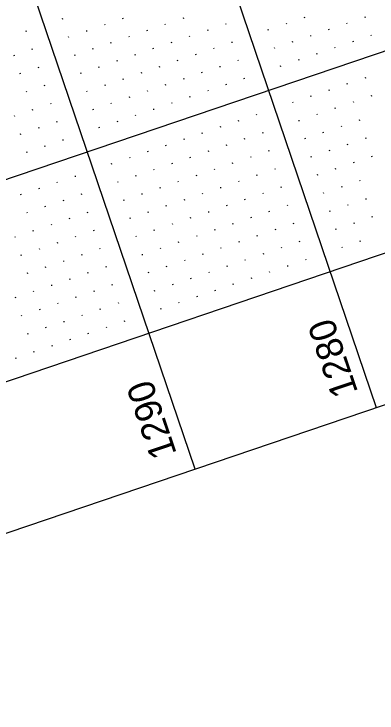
# Model space of a CAD drawing. Extents: x 2150318 to 2152065, y 143281 to 145371.
# Drawn here: x 2151642.9 to 2151737.7, y 143675.5 to 143858.1 of the extents above; entities that cross this region are included whole.
import ezdxf

# ---------------------------------------------------------------- set-up
doc = ezdxf.new("R2010")
doc.units = 0
for name, color, linetype in [('SHT_Plan_Profile_Sheet_Elev_Txt', 7, 'Continuous'), ('SHT_Profile_Grid_Major', 7, 'Continuous'), ('SHT_Profile_Grid_Minor', 7, 'Continuous'), ('SHT_Sheet_Border', 7, 'Continuous')]:
    doc.layers.add(name, color=color, linetype=linetype)

msp = doc.modelspace()

# ---------------------------------------------------------------- linework, layer by layer
at = {"layer": 'SHT_Profile_Grid_Major'}
for p, q in [((2151737.57, 143755.28), (2151231.58, 145246.79)), ((2151690.22, 143739.22), (2151184.23, 145230.73)), ((2151851.5, 143886.33), (2151378.01, 143725.7))]:
    msp.add_line(p, q, dxfattribs=at)
at = {"layer": 'SHT_Profile_Grid_Minor'}
for p, q in [((2151655.64, 143856.71), (2151655.56, 143856.95)), ((2151671.45, 143856.8), (2151671.37, 143857.03)), ((2151687.26, 143856.88), (2151687.18, 143857.12)), ((2151718.88, 143857.05), (2151718.8, 143857.28)), ((2151734.69, 143857.13), (2151734.61, 143857.37)), ((2151666.71, 143855.19), (2151666.63, 143855.43)), ((2151682.52, 143855.27), (2151682.44, 143855.51)), ((2151698.33, 143855.36), (2151698.25, 143855.59)), ((2151714.15, 143855.44), (2151714.07, 143855.68)), ((2151729.96, 143855.53), (2151729.88, 143855.76)), ((2151646.17, 143853.5), (2151646.09, 143853.74)), ((2151661.98, 143853.58), (2151661.9, 143853.82)), ((2151677.79, 143853.67), (2151677.71, 143853.9)), ((2151693.6, 143853.75), (2151693.52, 143853.99)), ((2151709.41, 143853.84), (2151709.33, 143854.07)), ((2151725.22, 143853.92), (2151725.14, 143854.16)), ((2151657.24, 143851.98), (2151657.16, 143852.21)), ((2151673.05, 143852.06), (2151672.97, 143852.3)), ((2151688.86, 143852.14), (2151688.78, 143852.38)), ((2151720.49, 143852.31), (2151720.41, 143852.55)), ((2151736.3, 143852.4), (2151736.22, 143852.63)), ((2151668.32, 143850.45), (2151668.24, 143850.69)), ((2151684.13, 143850.54), (2151684.05, 143850.78)), ((2151699.94, 143850.62), (2151699.86, 143850.86)), ((2151715.75, 143850.71), (2151715.67, 143850.94)), ((2151731.56, 143850.79), (2151731.48, 143851.03)), ((2151647.77, 143848.76), (2151647.69, 143849)), ((2151663.58, 143848.85), (2151663.5, 143849.09)), ((2151679.39, 143848.93), (2151679.31, 143849.17)), ((2151695.21, 143849.02), (2151695.13, 143849.25)), ((2151711.02, 143849.1), (2151710.94, 143849.34)), ((2151722.09, 143847.58), (2151722.01, 143847.81)), ((2151726.83, 143849.18), (2151726.75, 143849.42)), ((2151643.04, 143847.16), (2151642.96, 143847.39)), ((2151658.85, 143847.24), (2151658.77, 143847.48)), ((2151669.92, 143845.72), (2151669.84, 143845.96)), ((2151674.66, 143847.33), (2151674.58, 143847.56)), ((2151685.74, 143845.8), (2151685.66, 143846.04)), ((2151690.47, 143847.41), (2151690.39, 143847.65)), ((2151701.55, 143845.89), (2151701.47, 143846.12)), ((2151717.36, 143845.97), (2151717.28, 143846.21)), ((2151649.38, 143844.03), (2151649.3, 143844.27)), ((2151665.19, 143844.11), (2151665.11, 143844.35)), ((2151681, 143844.2), (2151680.92, 143844.43)), ((2151696.81, 143844.28), (2151696.73, 143844.52)), ((2151712.62, 143844.37), (2151712.54, 143844.6)), ((2151644.64, 143842.42), (2151644.56, 143842.66)), ((2151660.46, 143842.51), (2151660.37, 143842.74)), ((2151676.27, 143842.59), (2151676.19, 143842.83)), ((2151692.08, 143842.68), (2151692, 143842.91)), ((2151671.53, 143840.98), (2151671.45, 143841.22)), ((2151687.34, 143841.07), (2151687.26, 143841.31)), ((2151703.15, 143841.15), (2151703.07, 143841.39)), ((2151734.78, 143841.32), (2151734.7, 143841.56)), ((2151650.99, 143839.29), (2151650.9, 143839.53)), ((2151666.8, 143839.38), (2151666.72, 143839.62)), ((2151682.61, 143839.46), (2151682.53, 143839.7)), ((2151698.42, 143839.55), (2151698.34, 143839.78)), ((2151730.04, 143839.71), (2151729.96, 143839.95)), ((2151646.25, 143837.69), (2151646.17, 143837.92)), ((2151662.06, 143837.77), (2151661.98, 143838.01)), ((2151677.87, 143837.86), (2151677.79, 143838.09)), ((2151693.68, 143837.94), (2151693.6, 143838.18)), ((2151725.31, 143838.11), (2151725.23, 143838.34)), ((2151736.38, 143836.59), (2151736.3, 143836.82)), ((2151673.14, 143836.25), (2151673.06, 143836.49)), ((2151684.21, 143834.73), (2151684.13, 143834.96)), ((2151688.95, 143836.33), (2151688.87, 143836.57)), ((2151715.84, 143834.9), (2151715.76, 143835.13)), ((2151720.57, 143836.5), (2151720.49, 143836.74)), ((2151731.65, 143834.98), (2151731.57, 143835.22)), ((2151647.86, 143832.95), (2151647.78, 143833.19)), ((2151652.59, 143834.56), (2151652.51, 143834.8)), ((2151663.67, 143833.04), (2151663.59, 143833.27)), ((2151668.4, 143834.64), (2151668.32, 143834.88)), ((2151679.48, 143833.12), (2151679.4, 143833.36)), ((2151726.91, 143833.37), (2151726.83, 143833.61)), ((2151643.12, 143831.35), (2151643.04, 143831.58)), ((2151674.74, 143831.51), (2151674.66, 143831.75)), ((2151706.37, 143831.68), (2151706.29, 143831.92)), ((2151722.18, 143831.77), (2151722.1, 143832)), ((2151654.2, 143829.82), (2151654.12, 143830.06)), ((2151670.01, 143829.91), (2151669.93, 143830.15)), ((2151701.63, 143830.08), (2151701.55, 143830.31)), ((2151717.44, 143830.16), (2151717.36, 143830.4)), ((2151733.25, 143830.24), (2151733.17, 143830.48)), ((2151649.46, 143828.22), (2151649.38, 143828.46)), ((2151665.27, 143828.3), (2151665.19, 143828.54)), ((2151696.9, 143828.47), (2151696.82, 143828.71)), ((2151728.52, 143828.64), (2151728.44, 143828.87)), ((2151644.73, 143826.61), (2151644.65, 143826.85)), ((2151692.16, 143826.86), (2151692.08, 143827.1)), ((2151707.97, 143826.95), (2151707.89, 143827.18)), ((2151723.78, 143827.03), (2151723.7, 143827.27)), ((2151655.8, 143825.09), (2151655.72, 143825.33)), ((2151687.43, 143825.26), (2151687.35, 143825.49)), ((2151698.5, 143823.74), (2151698.42, 143823.97)), ((2151703.24, 143825.34), (2151703.16, 143825.58)), ((2151719.05, 143825.43), (2151718.97, 143825.66)), ((2151730.12, 143823.9), (2151730.04, 143824.14)), ((2151734.86, 143825.51), (2151734.78, 143825.75)), ((2151651.07, 143823.48), (2151650.99, 143823.72)), ((2151677.96, 143822.04), (2151677.88, 143822.28)), ((2151682.69, 143823.65), (2151682.61, 143823.89)), ((2151693.77, 143822.13), (2151693.69, 143822.37)), ((2151709.58, 143822.21), (2151709.5, 143822.45)), ((2151725.39, 143822.3), (2151725.31, 143822.53)), ((2151646.33, 143821.88), (2151646.25, 143822.11)), ((2151673.22, 143820.44), (2151673.14, 143820.68)), ((2151689.03, 143820.52), (2151688.95, 143820.76)), ((2151704.84, 143820.61), (2151704.76, 143820.84)), ((2151720.66, 143820.69), (2151720.57, 143820.93)), ((2151736.47, 143820.77), (2151736.39, 143821.01)), ((2151668.49, 143818.83), (2151668.41, 143819.07)), ((2151684.3, 143818.92), (2151684.22, 143819.15)), ((2151700.11, 143819), (2151700.03, 143819.24)), ((2151731.73, 143819.17), (2151731.65, 143819.41)), ((2151679.56, 143817.31), (2151679.48, 143817.55)), ((2151695.37, 143817.39), (2151695.29, 143817.63)), ((2151711.19, 143817.48), (2151711.1, 143817.71)), ((2151727, 143817.56), (2151726.92, 143817.8)), ((2151659.02, 143815.62), (2151658.94, 143815.86)), ((2151674.83, 143815.7), (2151674.75, 143815.94)), ((2151690.64, 143815.79), (2151690.56, 143816.02)), ((2151706.45, 143815.87), (2151706.37, 143816.11)), ((2151722.26, 143815.96), (2151722.18, 143816.19)), ((2151654.28, 143814.01), (2151654.2, 143814.25)), ((2151670.09, 143814.1), (2151670.01, 143814.33)), ((2151685.9, 143814.18), (2151685.82, 143814.42)), ((2151701.72, 143814.27), (2151701.63, 143814.5)), ((2151728.6, 143812.83), (2151728.52, 143813.06)), ((2151733.34, 143814.43), (2151733.26, 143814.67)), ((2151649.55, 143812.41), (2151649.47, 143812.64)), ((2151676.43, 143810.97), (2151676.35, 143811.21)), ((2151681.17, 143812.58), (2151681.09, 143812.81)), ((2151692.25, 143811.05), (2151692.16, 143811.29)), ((2151696.98, 143812.66), (2151696.9, 143812.9)), ((2151708.06, 143811.14), (2151707.98, 143811.37)), ((2151712.79, 143812.74), (2151712.71, 143812.98)), ((2151723.87, 143811.22), (2151723.79, 143811.46)), ((2151644.81, 143810.8), (2151644.73, 143811.04)), ((2151655.89, 143809.28), (2151655.81, 143809.52)), ((2151660.62, 143810.88), (2151660.54, 143811.12)), ((2151671.7, 143809.36), (2151671.62, 143809.6)), ((2151687.51, 143809.45), (2151687.43, 143809.68)), ((2151703.32, 143809.53), (2151703.24, 143809.77)), ((2151734.94, 143809.7), (2151734.86, 143809.94)), ((2151651.15, 143807.67), (2151651.07, 143807.91)), ((2151682.78, 143807.84), (2151682.7, 143808.08)), ((2151698.59, 143807.92), (2151698.51, 143808.16)), ((2151714.4, 143808.01), (2151714.32, 143808.24)), ((2151730.21, 143808.09), (2151730.13, 143808.33)), ((2151646.42, 143806.07), (2151646.34, 143806.3)), ((2151662.23, 143806.15), (2151662.15, 143806.39)), ((2151678.04, 143806.23), (2151677.96, 143806.47)), ((2151693.85, 143806.32), (2151693.77, 143806.55)), ((2151709.66, 143806.4), (2151709.58, 143806.64)), ((2151725.47, 143806.49), (2151725.39, 143806.72)), ((2151657.49, 143804.54), (2151657.41, 143804.78)), ((2151673.31, 143804.63), (2151673.23, 143804.86)), ((2151689.12, 143804.71), (2151689.04, 143804.95)), ((2151704.93, 143804.8), (2151704.85, 143805.03)), ((2151736.55, 143804.96), (2151736.47, 143805.2)), ((2151652.76, 143802.94), (2151652.68, 143803.17)), ((2151684.38, 143803.11), (2151684.3, 143803.34)), ((2151700.19, 143803.19), (2151700.11, 143803.43)), ((2151716, 143803.27), (2151715.92, 143803.51)), ((2151731.82, 143803.36), (2151731.73, 143803.59)), ((2151648.02, 143801.33), (2151647.94, 143801.57)), ((2151663.84, 143801.41), (2151663.76, 143801.65)), ((2151679.65, 143801.5), (2151679.57, 143801.74)), ((2151695.46, 143801.58), (2151695.38, 143801.82)), ((2151706.53, 143800.06), (2151706.45, 143800.3)), ((2151711.27, 143801.67), (2151711.19, 143801.9)), ((2151727.08, 143801.75), (2151727, 143801.99)), ((2151643.29, 143799.72), (2151643.21, 143799.96)), ((2151654.37, 143798.2), (2151654.29, 143798.44)), ((2151659.1, 143799.81), (2151659.02, 143800.05)), ((2151674.91, 143799.89), (2151674.83, 143800.13)), ((2151685.99, 143798.37), (2151685.91, 143798.61)), ((2151690.72, 143799.98), (2151690.64, 143800.21)), ((2151701.8, 143798.45), (2151701.72, 143798.69)), ((2151717.61, 143798.54), (2151717.53, 143798.77)), ((2151733.42, 143798.62), (2151733.34, 143798.86)), ((2151649.63, 143796.6), (2151649.55, 143796.83)), ((2151665.44, 143796.68), (2151665.36, 143796.92)), ((2151681.25, 143796.76), (2151681.17, 143797)), ((2151697.06, 143796.85), (2151696.98, 143797.08)), ((2151712.88, 143796.93), (2151712.8, 143797.17)), ((2151728.69, 143797.02), (2151728.61, 143797.25)), ((2151644.9, 143794.99), (2151644.82, 143795.23)), ((2151660.71, 143795.07), (2151660.63, 143795.31)), ((2151676.52, 143795.16), (2151676.44, 143795.39)), ((2151692.33, 143795.24), (2151692.25, 143795.48)), ((2151708.14, 143795.33), (2151708.06, 143795.56)), ((2151655.97, 143793.47), (2151655.89, 143793.7)), ((2151687.59, 143793.64), (2151687.51, 143793.87)), ((2151703.41, 143793.72), (2151703.33, 143793.96)), ((2151719.22, 143793.8), (2151719.14, 143794.04)), ((2151651.24, 143791.86), (2151651.16, 143792.1)), ((2151667.05, 143791.94), (2151666.97, 143792.18)), ((2151682.86, 143792.03), (2151682.78, 143792.27)), ((2151698.67, 143792.11), (2151698.59, 143792.35)), ((2151714.48, 143792.2), (2151714.4, 143792.43)), ((2151646.5, 143790.25), (2151646.42, 143790.49)), ((2151662.31, 143790.34), (2151662.23, 143790.58)), ((2151678.12, 143790.42), (2151678.04, 143790.66)), ((2151693.94, 143790.51), (2151693.86, 143790.74)), ((2151709.75, 143790.59), (2151709.67, 143790.83)), ((2151657.58, 143788.73), (2151657.5, 143788.97)), ((2151668.65, 143787.21), (2151668.57, 143787.45)), ((2151684.47, 143787.29), (2151684.39, 143787.53)), ((2151689.2, 143788.9), (2151689.12, 143789.14)), ((2151700.28, 143787.38), (2151700.2, 143787.61)), ((2151705.01, 143788.98), (2151704.93, 143789.22)), ((2151648.11, 143785.52), (2151648.03, 143785.76)), ((2151652.84, 143787.13), (2151652.76, 143787.36)), ((2151663.92, 143785.6), (2151663.84, 143785.84)), ((2151679.73, 143785.69), (2151679.65, 143785.92)), ((2151695.54, 143785.77), (2151695.46, 143786.01)), ((2151643.37, 143783.91), (2151643.29, 143784.15)), ((2151659.18, 143784), (2151659.1, 143784.23)), ((2151690.81, 143784.17), (2151690.73, 143784.4)), ((2151654.45, 143782.39), (2151654.37, 143782.63)), ((2151670.26, 143782.48), (2151670.18, 143782.71)), ((2151686.07, 143782.56), (2151685.99, 143782.8)), ((2151649.71, 143780.78), (2151649.63, 143781.02)), ((2151665.53, 143780.87), (2151665.45, 143781.11)), ((2151681.34, 143780.95), (2151681.26, 143781.19)), ((2151644.98, 143779.18), (2151644.9, 143779.42)), ((2151660.79, 143779.26), (2151660.71, 143779.5)), ((2151656.06, 143777.66), (2151655.98, 143777.89)), ((2151671.87, 143777.74), (2151671.79, 143777.98)), ((2151646.59, 143774.44), (2151646.51, 143774.68)), ((2151651.32, 143776.05), (2151651.24, 143776.29)), ((2151662.4, 143774.53), (2151662.32, 143774.76)), ((2151667.13, 143776.13), (2151667.05, 143776.37)), ((2151657.66, 143772.92), (2151657.58, 143773.16)), ((2151652.93, 143771.31), (2151652.85, 143771.55)), ((2151648.19, 143769.71), (2151648.11, 143769.95)), ((2151643.46, 143768.1), (2151643.38, 143768.34))]:
    msp.add_line(p, q, dxfattribs=at)
at = {"layer": 'SHT_Sheet_Border'}
msp.add_line((2151867.57, 143838.98), (2151394.07, 143678.35), dxfattribs=at)
msp.add_lwpolyline([(2150901.85, 143471.77), (2150395.86, 144963.28), (2151390.2, 145300.6), (2151896.19, 143809.09)], close=True, dxfattribs=at)

# ---------------------------------------------------------------- texts
at = {"layer": 'SHT_Plan_Profile_Sheet_Elev_Txt'}
for s, p in [('1280', (2151732.84, 143759.38)), ('1290', (2151685.49, 143743.31))]:
    msp.add_text(s, height=7, rotation=108.7393, dxfattribs=at).set_placement(p)

doc.saveas('drawing.dxf')
